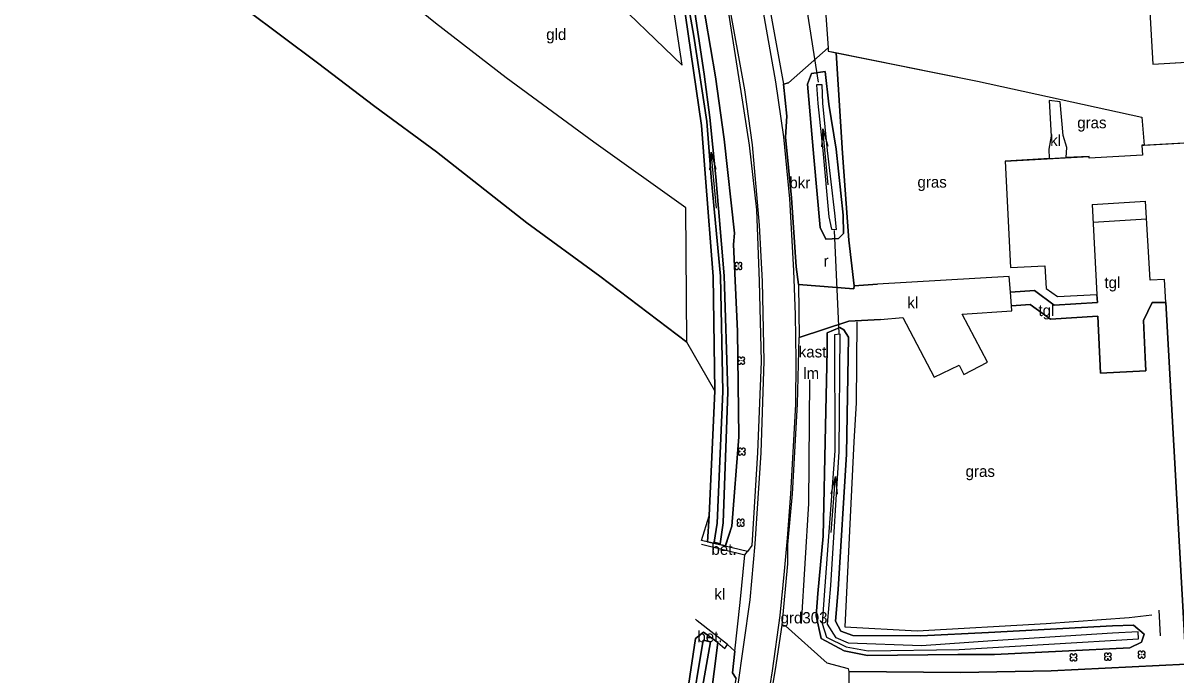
# Model space of a CAD drawing. Extents: x 154825 to 158680, y 370717 to 378075.
# Drawn here: x 155413 to 155515.3, y 377201.9 to 377259.7 of the extents above; entities that cross this region are included whole.
import ezdxf

# ---------------------------------------------------------------- set-up
doc = ezdxf.new("R2010")
doc.units = 0
for name, color, linetype in [('boom', 7, 'Continuous'), ('brandkr(bovengr)', 7, 'Continuous'), ('breuklijn', 7, 'Continuous'), ('deelstreep(1-3)', 7, 'Continuous'), ('duiker lijn', 7, 'Continuous'), ('gebouw algemeen', 7, 'Continuous'), ('grasland_productiegrasl(vs)', 7, 'Continuous'), ('grazige vegetatie(vs)', 7, 'Continuous'), ('haag geschoren', 7, 'Continuous'), ('hoogteverschillijn', 7, 'Continuous'), ('insteek sloot', 7, 'Continuous'), ('kast_huis punt', 7, 'Continuous'), ('klinkerverharding(vs)', 7, 'Continuous'), ('maaiveldlijn algemeen - gesloten verharding', 7, 'Continuous'), ('maaiveldlijn algemeen - open verharding', 7, 'Continuous'), ('maaiveldlijn algemeen - tegelverharding', 7, 'Continuous'), ('maaiveldlijn algemeen - verharding algemeen', 7, 'Continuous'), ('rioolput(z_inl)', 7, 'Continuous'), ('Sloot bodem', 7, 'Continuous'), ('stroomrichting  watergangen', 7, 'Continuous'), ('tegelverh(vs)', 7, 'Continuous'), ('verlichtingsobject', 7, 'Continuous'), ('vlak_akkerland', 7, 'Continuous'), ('vlak_Grazige_vegetatie', 7, 'Continuous')]:
    doc.layers.add(name, color=color, linetype=linetype)

msp = doc.modelspace()

# ---------------------------------------------------------------- linework, layer by layer
at = {"layer": 'boom'}
for centre in [(155476.46, 377238.14), (155476.7, 377229.74), (155476.76, 377221.68), (155476.66, 377215.36), (155506.18, 377203.41), (155509.23, 377203.48), (155512.23, 377203.66)]:
    msp.add_circle(centre, 0.006, dxfattribs=at)
for centre, start, end in [((155476.3, 377238.3), 357.075, 272.925), ((155476.3, 377237.99), 87.075, 2.925), ((155476.62, 377238.3), 267.075, 182.925), ((155476.62, 377237.99), 177.075, 92.925), ((155476.54, 377229.9), 357.075, 272.925), ((155476.54, 377229.58), 87.075, 2.925), ((155476.86, 377229.9), 267.075, 182.925), ((155476.86, 377229.58), 177.075, 92.925), ((155476.6, 377221.83), 357.075, 272.925), ((155476.6, 377221.52), 87.075, 2.925), ((155476.92, 377221.83), 267.075, 182.925), ((155476.92, 377221.52), 177.075, 92.925), ((155476.5, 377215.52), 357.075, 272.925), ((155476.5, 377215.2), 87.075, 2.925), ((155476.82, 377215.52), 267.075, 182.925), ((155476.82, 377215.2), 177.075, 92.925), ((155509.08, 377203.64), 357.075, 272.925), ((155509.39, 377203.64), 267.075, 182.925), ((155512.07, 377203.82), 357.075, 272.925), ((155512.38, 377203.82), 267.075, 182.925), ((155506.02, 377203.56), 357.075, 272.925), ((155506.02, 377203.25), 87.075, 2.925), ((155506.34, 377203.56), 267.075, 182.925), ((155506.34, 377203.25), 177.075, 92.925), ((155509.08, 377203.32), 87.075, 2.925), ((155509.39, 377203.32), 177.075, 92.925), ((155512.07, 377203.5), 87.075, 2.925), ((155512.38, 377203.5), 177.075, 92.925)]:
    msp.add_arc(centre, 0.158, start, end, dxfattribs=at)
at = {"layer": 'breuklijn'}
msp.add_lwpolyline([(155482.05, 377206.42), (155482.71, 377217.08), (155482.79, 377228.03)], dxfattribs=at)
at = {"layer": 'deelstreep(1-3)'}
for points in [[(155437.66, 377480.71), (155438.16, 377472.53), (155439.59, 377460.39), (155441.45, 377448.89), (155445.6, 377425.35), (155447.26, 377416.5), (155450.91, 377396.55), (155455.12, 377373.55), (155458.93, 377352.67), (155463.84, 377325.72), (155466.95, 377308.73), (155469.14, 377296.77), (155472.64, 377277.72), (155474.84, 377265.78), (155475.54, 377261.77), (155476.99, 377253.79), (155477.67, 377248.89), (155478.31, 377241.77), (155478.57, 377236.78), (155478.71, 377229.69), (155478.45, 377221.57), (155477.91, 377213.49), (155477.46, 377208.51), (155476.34, 377200.59)], [(155462.05, 377351.58), (155466.44, 377327.46), (155469.8, 377308.98), (155472.14, 377296.34), (155475.52, 377277.86), (155477.68, 377266.19), (155479.75, 377254.48), (155480.46, 377249.6), (155480.99, 377244.11), (155481.36, 377237.76), (155481.48, 377233.8), (155481.56, 377229.8), (155481.51, 377225.86), (155481.08, 377217.93), (155480.79, 377214), (155480.51, 377211.05), (155480.12, 377207.12), (155479.46, 377202.23), (155478.84, 377198.3)]]:
    msp.add_lwpolyline(points, dxfattribs=at)
at = {"layer": 'duiker lijn'}
for points in [[(155483.57, 377254.47), (155481.78, 377265.83)], [(155485.39, 377232.15), (155484.99, 377241.3)]]:
    msp.add_lwpolyline(points, dxfattribs=at)
at = {"layer": 'gebouw algemeen'}
for points in [[(155512.21, 377273.72), (155513.23, 377256.06)], [(155513.23, 377256.06), (155551.28, 377258.31), (155571.55, 377259.51)], [(155513.23, 377256.06), (155571.55, 377259.51)], [(155512.25, 377248.86), (155512.44, 377248.87), (155536.24, 377250.21)], [(155512.25, 377248.86), (155536.24, 377250.21)], [(155512.25, 377248.86), (155512.3, 377247.98), (155507.58, 377247.71), (155507.57, 377247.87)], [(155500.11, 377247.46), (155504.03, 377247.68), (155505.54, 377247.76), (155507.57, 377247.87)], [(155500.11, 377247.46), (155507.57, 377247.87)], [(155500.11, 377247.46), (155500.6, 377238.01), (155503.65, 377238.17), (155503.76, 377236.14), (155504.75, 377235.43), (155508.26, 377235.62)], [(155507.83, 377243.61), (155512.57, 377243.9)], [(155514.38, 377234.9), (155514.26, 377236.96), (155512.97, 377236.89), (155512.57, 377243.9)], [(155507.83, 377243.61), (155508.26, 377235.62)], [(155507.92, 377242.04), (155512.67, 377242.33)], [(155516.05, 377204.77), (155514.38, 377234.9)], [(155513.89, 377205.31), (155513.78, 377207.6)]]:
    msp.add_lwpolyline(points, dxfattribs=at)
at = {"layer": 'haag geschoren'}
for points in [[(155485.13, 377257.07), (155485.68, 377248.17), (155486.26, 377240.44), (155486.73, 377236.38)], [(155486.96, 377233.2), (155486.91, 377226.01), (155486.71, 377222.53), (155485.91, 377206.12), (155492.3, 377205.77), (155503.77, 377206.41), (155511.13, 377206.95), (155513.14, 377207.2)]]:
    msp.add_lwpolyline(points, dxfattribs=at)
at = {"layer": 'hoogteverschillijn'}
msp.add_lwpolyline([(155432.8, 377260.92), (155439.14, 377256.17), (155444.2, 377252.29), (155449.68, 377248.27), (155457.69, 377241.99), (155464.16, 377237.25), (155471.89, 377231.38), (155471.8, 377243.3), (155463.63, 377249.13), (155455.87, 377254.84), (155449.58, 377259.71), (155440.91, 377266.78), (155450.66, 377273.2), (155457.18, 377268), (155464.35, 377262.86), (155471.47, 377255.97), (155469.77, 377267.3), (155462.85, 377274.16), (155458.26, 377278.25), (155466.03, 377283.43), (155468.3, 377274.3)], dxfattribs=at)
at = {"layer": 'insteek sloot'}
for points in [[(155475.29, 377213.28), (155475.87, 377215.06), (155476.5, 377222.98), (155476.37, 377232.37), (155476.01, 377240.04), (155476.11, 377241.07), (155475.21, 377249.41), (155474.43, 377254.94), (155473.11, 377262.77), (155469.79, 377279.88), (155469.3, 377279.98), (155468.26, 377279.52)], [(155468.26, 377279.52), (155469.42, 377273.35), (155471.29, 377263.65), (155473.2, 377250.62), (155473.54, 377245.96), (155474.22, 377237.22), (155474.36, 377227.08), (155473.88, 377215.97), (155473.73, 377213.67)], [(155485.74, 377242.65), (155485.78, 377241.02), (155485.34, 377240.59), (155484.22, 377240.52), (155483.7, 377241.55), (155483.14, 377247.79), (155482.6, 377254.27), (155482.95, 377255.22), (155484.14, 377255.4), (155484.47, 377252.51), (155485.14, 377248.5), (155485.74, 377242.65)], [(155483.5, 377209.07), (155483.37, 377207.09), (155483.81, 377205.08), (155485.85, 377203.98), (155487.92, 377203.59), (155495.92, 377203.66), (155499.16, 377203.67), (155511.18, 377204.26), (155512.21, 377204.75), (155512.44, 377205.46), (155511.5, 377206.27), (155509.63, 377206.21), (155498.64, 377205.62), (155492.64, 377205.32), (155486.61, 377205.36), (155485.53, 377205.73), (155485.07, 377206.62), (155485.31, 377209.43), (155486.05, 377221.46), (155486.21, 377231.82), (155485.81, 377232.48), (155485.46, 377232.68), (155484.34, 377232.21), (155484.33, 377230.65), (155484.18, 377223.92), (155483.97, 377214.16), (155483.5, 377209.07)], [(155473.63, 377196.77), (155474.63, 377204.73), (155473.35, 377205.64), (155472.64, 377205.08), (155471.93, 377200.33)]]:
    msp.add_lwpolyline(points, dxfattribs=at)
at = {"layer": 'maaiveldlijn algemeen - gesloten verharding'}
for points in [[(155458.76, 377352.51), (155463.59, 377325.7), (155466.67, 377309), (155467.38, 377303.8), (155467.58, 377302.21), (155468.05, 377299.13), (155469.07, 377295.72), (155472.42, 377277.7), (155474.61, 377266.05), (155475.4, 377261.7), (155476.67, 377253.63), (155477.41, 377248.86), (155478.05, 377243.13), (155478.3, 377236.8), (155478.48, 377229.66), (155478.15, 377221.59), (155477.65, 377213.33), (155477.27, 377212.82)], [(155478.57, 377264.72), (155480.45, 377254.28)], [(155480.45, 377254.28), (155480.75, 377251.43), (155480.63, 377249.57), (155481.17, 377244.19), (155481.59, 377238.06), (155481.79, 377236.5)], [(155481.79, 377236.5), (155481.84, 377231.81)], [(155480.35, 377206.28), (155480.85, 377211.71), (155480.83, 377213.43), (155481.25, 377217.94), (155481.7, 377225.89), (155481.84, 377231.81)], [(155476.13, 377203.97), (155476.61, 377208.29), (155477.03, 377212.5)], [(155478.9, 377197.23), (155479.75, 377202.33), (155480.35, 377206.28)], [(155339.84, 377033.84), (155360, 377049.28), (155369.93, 377056.87), (155370.58, 377057.63), (155376.54, 377062.35), (155377.67, 377062.8), (155394.51, 377075.81), (155408.3, 377086.49), (155419.93, 377096.32), (155428.54, 377104.47), (155436.64, 377113.59), (155444.15, 377123.01), (155449.26, 377130.55), (155455.11, 377140.02), (155460.57, 377150.71), (155465.67, 377162.76), (155469.64, 377174.1), (155472.88, 377185.78), (155476.1, 377200.56), (155476.25, 377201.54), (155475.94, 377202.03), (155476.13, 377203.97)]]:
    msp.add_lwpolyline(points, dxfattribs=at)
at = {"layer": 'maaiveldlijn algemeen - open verharding'}
for points in [[(155483.91, 377264.51), (155484.41, 377257.5)], [(155484.41, 377257.5), (155480.89, 377254.4), (155480.45, 377254.28)], [(155486.73, 377236.38), (155488.79, 377236.53)], [(155481.79, 377236.5), (155486.7, 377236.13), (155486.73, 377236.38)], [(155489.05, 377233.41), (155486.24, 377233.25), (155481.84, 377231.81)], [(155473.18, 377213.45), (155477.03, 377212.5)], [(155475.49, 377204.55), (155472.81, 377206.65), (155472.66, 377206.81)], [(155486.26, 377199.9), (155486.29, 377202.16), (155486.22, 377202.39), (155484.34, 377202.89), (155480.65, 377206.2), (155480.35, 377206.28)], [(155476.13, 377203.97), (155475.49, 377204.55)]]:
    msp.add_lwpolyline(points, dxfattribs=at)
at = {"layer": 'maaiveldlijn algemeen - tegelverharding'}
for points in [[(155500.58, 377235.82), (155502.73, 377235.97), (155504.48, 377234.67), (155508.3, 377234.91), (155508.26, 377235.62)], [(155508.34, 377233.69), (155504.15, 377233.43), (155502.35, 377234.74), (155500.67, 377234.62)], [(155514.38, 377234.9), (155513.16, 377234.9), (155512.38, 377233.31), (155512.53, 377230.04), (155512.6, 377228.84), (155508.59, 377228.63), (155508.34, 377233.69)]]:
    msp.add_lwpolyline(points, dxfattribs=at)
at = {"layer": 'maaiveldlijn algemeen - verharding algemeen'}
for points in [[(155484.41, 377257.5), (155484.43, 377257.21), (155485.13, 377257.07), (155497.68, 377254.55)], [(155484.63, 377257.17), (155497.68, 377254.55)], [(155497.68, 377254.55), (155512.25, 377251.34), (155512.44, 377248.87)], [(155505.54, 377247.76), (155505.58, 377248.66), (155505.25, 377249.73), (155505, 377252.71), (155504.02, 377252.82), (155504.21, 377249.66), (155503.98, 377248.52), (155504.03, 377247.68)], [(155500.58, 377235.82), (155500.48, 377237.21), (155488.79, 377236.53)], [(155500.67, 377234.62), (155500.58, 377235.82)], [(155489.05, 377233.41), (155491.04, 377233.56), (155493.82, 377228.27), (155496.03, 377229.34), (155496.45, 377228.53), (155498.54, 377229.62), (155496.32, 377233.88), (155500.71, 377234.17), (155500.67, 377234.62)], [(155477.03, 377212.5), (155477.27, 377212.82), (155473.19, 377213.79)], [(155474.63, 377204.73), (155475.25, 377204.2), (155475.49, 377204.55)], [(155486.29, 377202.16), (155496.19, 377202.07), (155504.2, 377202.23), (155516.16, 377202.81)]]:
    msp.add_lwpolyline(points, dxfattribs=at)
at = {"layer": 'Sloot bodem'}
for points in [[(155472.52, 377258.55), (155470.57, 377269.45), (155468.78, 377279.52), (155469.21, 377279.69), (155470.91, 377269.61), (155472.41, 377261.87), (155473.42, 377255.18), (155473.92, 377251.33), (155474.45, 377246.07), (155475.21, 377237.27), (155475.53, 377226.97), (155475.12, 377215.34), (155474.85, 377213.48), (155474.3, 377213.63), (155474.57, 377215.33), (155475.07, 377227), (155474.86, 377237.25), (155474.04, 377246.02), (155473.67, 377250.97), (155472.52, 377258.55)], [(155484.47, 377242.52), (155484.71, 377241.42), (155485.17, 377241.39), (155485, 377242.84), (155484.35, 377248.4), (155483.95, 377252.61), (155483.9, 377254.23), (155483.39, 377254.21), (155483.51, 377252.57), (155483.96, 377248.39), (155484.47, 377242.52)], [(155484.08, 377208.94), (155483.89, 377206.42), (155484.28, 377205.22), (155486.03, 377204.34), (155487.96, 377203.98), (155496.05, 377204.11), (155511.95, 377205.05), (155511.91, 377205.69), (155509.65, 377205.55), (155498.99, 377204.89), (155492.69, 377204.44), (155486.22, 377204.67), (155485.14, 377205.16), (155484.35, 377206.35), (155484.65, 377209.8), (155485.39, 377221.68), (155485.48, 377232.1), (155484.99, 377232.05), (155485, 377221.75), (155484.08, 377208.94)], [(155472.19, 377197.95), (155473.32, 377204.93), (155473.97, 377204.79), (155472.63, 377197.06)]]:
    msp.add_lwpolyline(points, dxfattribs=at)
at = {"layer": 'stroomrichting  watergangen'}
for p, q in [((155483.95, 377250.29), (155483.82, 377248.72)), ((155484.43, 377245.34), (155483.96, 377250.31)), ((155483.96, 377250.31), (155484.38, 377248.79)), ((155474.04, 377248.24), (155473.91, 377246.67)), ((155474.52, 377243.29), (155474.05, 377248.26)), ((155474.05, 377248.26), (155474.47, 377246.73)), ((155485.05, 377219.46), (155484.66, 377217.93)), ((155484.7, 377214.49), (155485.06, 377219.47)), ((155485.06, 377219.47), (155485.22, 377217.9))]:
    msp.add_line(p, q, dxfattribs=at)
at = {"layer": 'vlak_akkerland'}
msp.add_lwpolyline([(155474.22, 377237.22), (155474.36, 377227.08), (155471.89, 377231.38), (155464.16, 377237.25), (155457.69, 377241.99), (155449.68, 377248.27), (155444.2, 377252.29), (155439.14, 377256.17), (155432.8, 377260.92), (155429.17, 377261.12), (155448.93, 377273.77), (155465.51, 377284.74), (155466.84, 377284.77), (155467.59, 377281.92), (155468.26, 377279.52), (155469.42, 377273.35), (155471.29, 377263.65), (155473.2, 377250.62), (155473.54, 377245.96)], close=True, dxfattribs=at)
at = {"layer": 'vlak_Grazige_vegetatie'}
for points in [[(155469.79, 377279.88), (155473.11, 377262.77), (155474.43, 377254.94), (155475.21, 377249.41), (155476.11, 377241.07), (155476.01, 377240.04), (155476.37, 377232.37), (155476.5, 377222.98), (155475.87, 377215.06), (155475.3, 377213.32), (155473.73, 377213.67), (155473.88, 377215.97), (155474.36, 377227.08), (155474.22, 377237.22), (155473.54, 377245.96), (155473.2, 377250.62), (155471.29, 377263.65), (155469.42, 377273.35), (155468.26, 377279.52), (155469.3, 377279.98)], [(155474.3, 377213.63), (155474.85, 377213.48), (155475.12, 377215.34), (155475.53, 377226.97), (155475.21, 377237.27), (155474.45, 377246.07), (155473.92, 377251.33), (155473.42, 377255.18), (155472.41, 377261.87), (155470.91, 377269.61), (155469.21, 377279.69), (155468.78, 377279.52), (155470.57, 377269.45), (155472.52, 377258.55), (155473.67, 377250.97), (155474.04, 377246.02), (155474.86, 377237.25), (155475.07, 377227), (155474.57, 377215.33)], [(155485.13, 377257.07), (155485.68, 377248.17), (155486.26, 377240.44), (155486.73, 377236.38), (155486.7, 377236.13), (155481.79, 377236.5), (155481.59, 377238.06), (155481.17, 377244.19), (155480.63, 377249.57), (155480.75, 377251.43), (155480.45, 377254.28), (155480.89, 377254.4), (155484.41, 377257.5), (155484.43, 377257.21)], [(155497.68, 377254.55), (155512.25, 377251.34), (155512.44, 377248.87), (155512.25, 377248.86), (155512.3, 377247.98), (155507.58, 377247.71), (155507.57, 377247.87), (155505.54, 377247.76), (155505.58, 377248.66), (155505.25, 377249.73), (155505, 377252.71), (155504.02, 377252.82), (155504.21, 377249.66), (155503.98, 377248.52), (155504.03, 377247.68), (155500.11, 377247.46), (155500.6, 377238.01), (155503.65, 377238.17), (155503.76, 377236.14), (155504.75, 377235.43), (155508.26, 377235.62), (155508.3, 377234.91), (155504.48, 377234.67), (155502.73, 377235.97), (155500.58, 377235.82), (155500.48, 377237.21), (155488.79, 377236.53), (155486.73, 377236.38), (155486.26, 377240.44), (155485.68, 377248.17), (155485.13, 377257.07)], [(155484.14, 377255.4), (155484.47, 377252.51), (155485.14, 377248.5), (155485.74, 377242.65), (155485.78, 377241.02), (155485.34, 377240.59), (155484.22, 377240.52), (155483.7, 377241.55), (155483.14, 377247.79), (155482.6, 377254.27), (155482.95, 377255.22)], [(155483.7, 377241.55), (155484.22, 377240.52), (155485.34, 377240.59), (155485.78, 377241.02), (155485.74, 377242.65), (155485.14, 377248.5), (155484.47, 377252.51), (155484.14, 377255.4), (155482.95, 377255.22), (155482.6, 377254.27), (155483.14, 377247.79)], [(155484.71, 377241.42), (155485.17, 377241.39), (155485, 377242.84), (155484.35, 377248.4), (155483.95, 377252.61), (155483.9, 377254.23), (155483.39, 377254.21), (155483.51, 377252.57), (155483.96, 377248.39), (155484.47, 377242.52)], [(155485.81, 377232.48), (155485.46, 377232.68), (155484.34, 377232.21), (155484.33, 377230.65), (155484.18, 377223.92), (155483.97, 377214.16), (155483.5, 377209.07), (155483.37, 377207.09), (155483.81, 377205.08), (155485.85, 377203.98), (155487.92, 377203.59), (155495.92, 377203.66), (155499.16, 377203.67), (155511.18, 377204.26), (155512.21, 377204.75), (155512.44, 377205.46), (155511.5, 377206.27), (155509.63, 377206.21), (155498.64, 377205.62), (155492.64, 377205.32), (155486.61, 377205.36), (155485.53, 377205.73), (155485.07, 377206.62), (155485.31, 377209.43), (155486.05, 377221.46), (155486.21, 377231.82)], [(155485.81, 377232.48), (155486.21, 377231.82), (155486.05, 377221.46), (155485.31, 377209.43), (155485.07, 377206.62), (155485.53, 377205.73), (155486.61, 377205.36), (155492.64, 377205.32), (155498.64, 377205.62), (155509.63, 377206.21), (155511.5, 377206.27), (155512.44, 377205.46), (155512.21, 377204.75), (155511.18, 377204.26), (155499.16, 377203.67), (155495.92, 377203.66), (155487.92, 377203.59), (155485.85, 377203.98), (155483.81, 377205.08), (155483.37, 377207.09), (155483.5, 377209.07), (155483.97, 377214.16), (155484.18, 377223.92), (155484.33, 377230.65), (155484.34, 377232.21), (155485.46, 377232.68)], [(155486.03, 377204.34), (155487.96, 377203.98), (155496.05, 377204.11), (155511.95, 377205.05), (155511.91, 377205.69), (155509.65, 377205.55), (155498.99, 377204.89), (155492.69, 377204.44), (155486.22, 377204.67), (155485.14, 377205.16), (155484.35, 377206.35), (155484.65, 377209.8), (155485.39, 377221.68), (155485.48, 377232.1), (155484.99, 377232.05), (155485, 377221.75), (155484.08, 377208.94), (155483.89, 377206.42), (155484.28, 377205.22)]]:
    msp.add_lwpolyline(points, close=True, dxfattribs=at)
for points in [[(155475.4, 377261.7), (155476.67, 377253.63), (155477.41, 377248.86), (155478.05, 377243.13), (155478.3, 377236.8), (155478.48, 377229.66), (155478.15, 377221.59), (155477.65, 377213.33), (155477.27, 377212.82), (155473.19, 377213.79), (155473.88, 377215.97), (155473.73, 377213.67), (155475.3, 377213.32), (155475.87, 377215.06), (155476.5, 377222.98), (155476.37, 377232.37), (155476.01, 377240.04), (155476.11, 377241.07), (155475.21, 377249.41), (155474.43, 377254.94), (155473.11, 377262.77)], [(155516.16, 377202.81), (155504.2, 377202.23), (155496.19, 377202.07), (155486.29, 377202.16), (155486.22, 377202.39), (155484.34, 377202.89), (155480.65, 377206.2), (155480.35, 377206.28), (155480.85, 377211.71), (155480.83, 377213.43), (155481.25, 377217.94), (155481.7, 377225.89), (155481.84, 377231.81), (155486.24, 377233.25), (155489.05, 377233.41), (155491.04, 377233.56), (155493.82, 377228.27), (155496.03, 377229.34), (155496.45, 377228.53), (155498.54, 377229.62), (155496.32, 377233.88), (155500.71, 377234.17), (155500.67, 377234.62), (155502.35, 377234.74), (155504.15, 377233.43), (155508.34, 377233.69), (155508.59, 377228.63), (155512.6, 377228.84), (155512.53, 377230.04), (155512.38, 377233.31), (155513.16, 377234.9), (155514.38, 377234.9), (155516.05, 377204.77)], [(155471.93, 377200.33), (155472.64, 377205.08), (155473.35, 377205.64), (155474.63, 377204.73), (155473.63, 377196.77)], [(155472.63, 377197.06), (155473.97, 377204.79), (155473.32, 377204.93), (155472.19, 377197.95)], [(155473.63, 377196.77), (155474.63, 377204.73), (155475.25, 377204.2), (155475.49, 377204.55), (155476.13, 377203.97), (155475.94, 377202.03), (155476.25, 377201.54)]]:
    msp.add_lwpolyline(points, dxfattribs=at)

# ---------------------------------------------------------------- texts
at = {"layer": 'brandkr(bovengr)'}
msp.add_text('bkr', height=1, dxfattribs=at).set_placement((155480.98, 377245.04))
at = {"layer": 'grasland_productiegrasl(vs)'}
msp.add_text('gld', height=1, dxfattribs=at).set_placement((155459.41, 377258.2))
at = {"layer": 'grazige vegetatie(vs)'}
for p in [(155506.51, 377250.37), (155492.34, 377245.1), (155496.61, 377219.43)]:
    msp.add_text('gras', height=1, dxfattribs=at).set_placement(p)
at = {"layer": 'kast_huis punt'}
msp.add_text('kast', height=1, dxfattribs=at).set_placement((155481.81, 377230.03))
at = {"layer": 'klinkerverharding(vs)'}
for s, p in [('kl', (155504.11, 377248.79)), ('kl', (155491.44, 377234.4)), ('bet.', (155474.07, 377212.51)), ('kl', (155474.33, 377208.53)), ('bet.', (155472.82, 377204.76))]:
    msp.add_text(s, height=1, dxfattribs=at).set_placement(p)
at = {"layer": 'rioolput(z_inl)'}
msp.add_text('r', height=1, dxfattribs=at).set_placement((155484.01, 377238.1))
at = {"layer": 'tegelverh(vs)'}
for p in [(155508.92, 377236.18), (155503.07, 377233.7)]:
    msp.add_text('tgl', height=1, dxfattribs=at).set_placement(p)
at = {"layer": 'verlichtingsobject'}
for s, p in [('lm', (155482.21, 377228.13)), ('grd303', (155480.2, 377206.43)), ('grd303', (155480.2, 377206.43))]:
    msp.add_text(s, height=1, dxfattribs=at).set_placement(p)

doc.saveas('drawing.dxf')
